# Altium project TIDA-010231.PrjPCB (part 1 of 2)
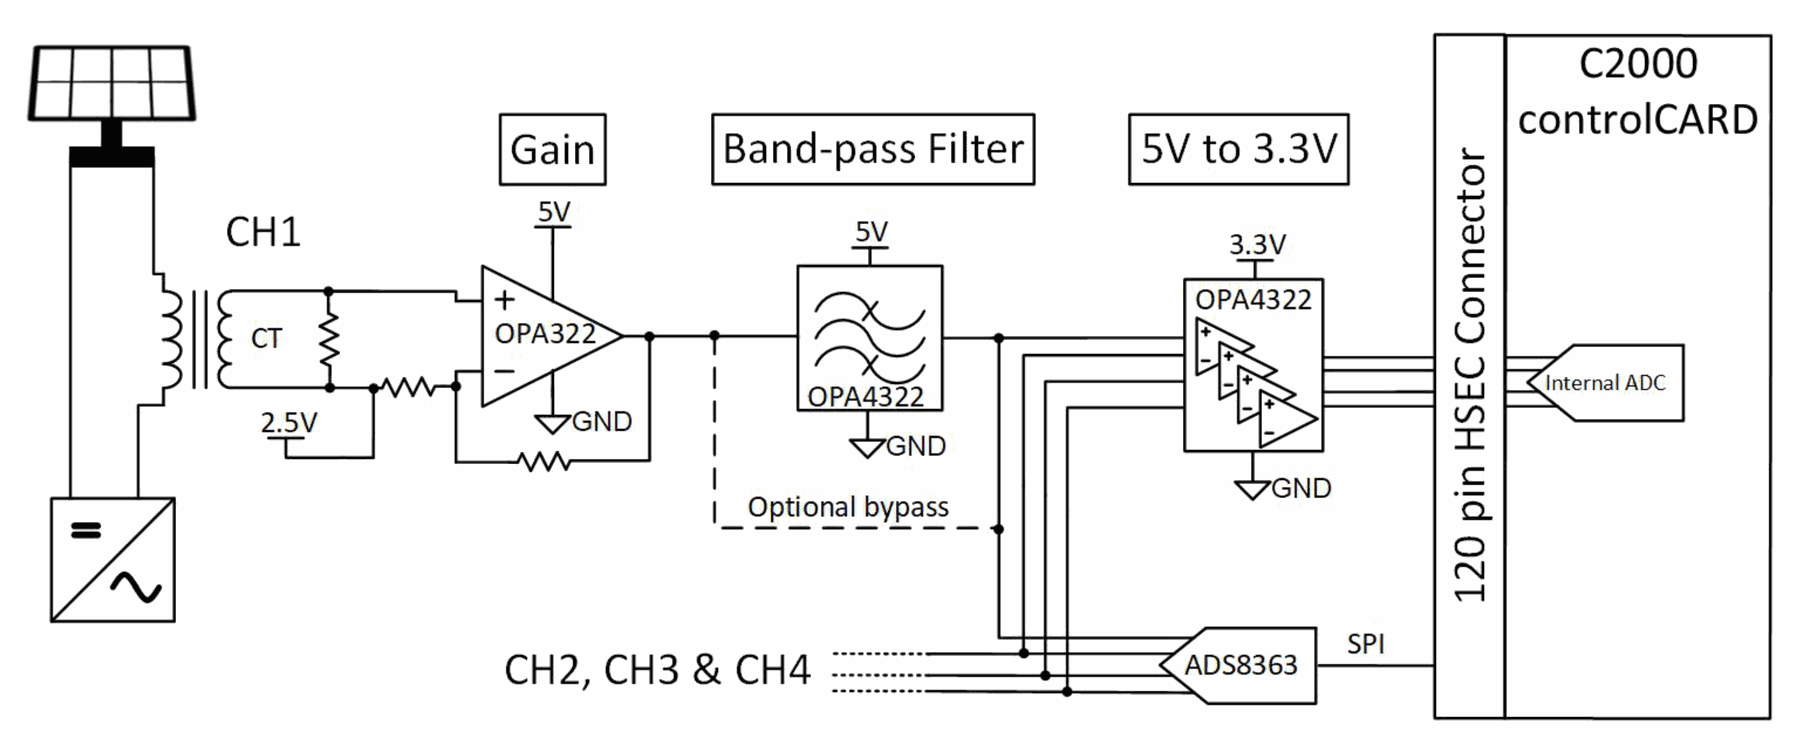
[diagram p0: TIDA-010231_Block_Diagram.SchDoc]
CopyrightYear: 2022; DrawnBy: Andreas Lechner; EVM_orderable: N/A; PCB_Layout: Andreas Lechner; PCB_Rev: E1; PRJ_Customer: Public Release; PRJ_Engineer: Andreas Lechner; PRJ_Number: TIDA-010231; PRJ_Title: TIDA-010231; SCH_Rev: E1; TechSupport: http://www.ti.com/support; TID: TIDA-010231
6 sheets, 296 parts. Net scope: global (net labels, ports and power ports of the same name join across sheets).
Board file: TIDA-010231_PCB.PcbDoc
Sheets:
  TIDA-010231_Block_Diagram.SchDoc
  TIDA-010231_Power.SchDoc
  TIDA-010231_Filter_and_ADC.SchDoc
  TIDA-010231_Current_Transformer.SchDoc
  TIDA-010231_Interface.SchDoc
  TIDA-010231_Hardware.SchDoc

## Sheet TIDA-010231_Block_Diagram.SchDoc: Block Diagram
size 431 x 279 mm; Date: Not shown in title block; ApprovedBy: Not shown in title block; CheckedBy: Not shown in title block; Author: Not shown in title block; CompanyName: Not shown in title block; Engineer: Not shown in title block; Organization: Not shown in title block; Address1: Not shown in title block; Address2: Not shown in title block; Address3: Not shown in title block; Address4: Not shown in title block; DocumentNumber: 1; Revision: Use project parameter SCH_Rev; SheetNumber: 1; SheetTotal: 6; PageSetup: Record=PageOptions¦CenterHorizontal=True¦CenterVertical=True¦PrintScale=1.00¦XCorrection=1.00¦YCorrection=1.00¦PrintKind=0¦BorderSize=5000000¦LeftOffset=0¦BottomOffset=0¦Orientation=2¦PaperLength=1000¦PaperWidth=1000¦Scale=100¦PaperSource=15¦PrintQuality=600¦MediaType=1¦DitherType=10¦PaperKind=Letter¦PrintScaleMode=1

## Sheet TIDA-010231_Power.SchDoc: Power
size 431 x 279 mm; Date: Not shown in title block; ApprovedBy: Not shown in title block; CheckedBy: Not shown in title block; Author: Not shown in title block; CompanyName: Not shown in title block; Engineer: Not shown in title block; Organization: Not shown in title block; Address1: Not shown in title block; Address2: Not shown in title block; Address3: Not shown in title block; Address4: Not shown in title block; DocumentNumber: 2; Revision: Use project parameter SCH_Rev; SheetNumber: 2; SheetTotal: 6; PageSetup: Record=PageOptions¦CenterHorizontal=True¦CenterVertical=True¦PrintScale=1.00¦XCorrection=1.00¦YCorrection=1.00¦PrintKind=0¦BorderSize=5000000¦LeftOffset=0¦BottomOffset=0¦Orientation=2¦PaperLength=1000¦PaperWidth=1000¦Scale=100¦PaperSource=15¦PrintQuality=600¦MediaType=1¦DitherType=10¦PaperKind=Letter¦PrintScaleMode=1
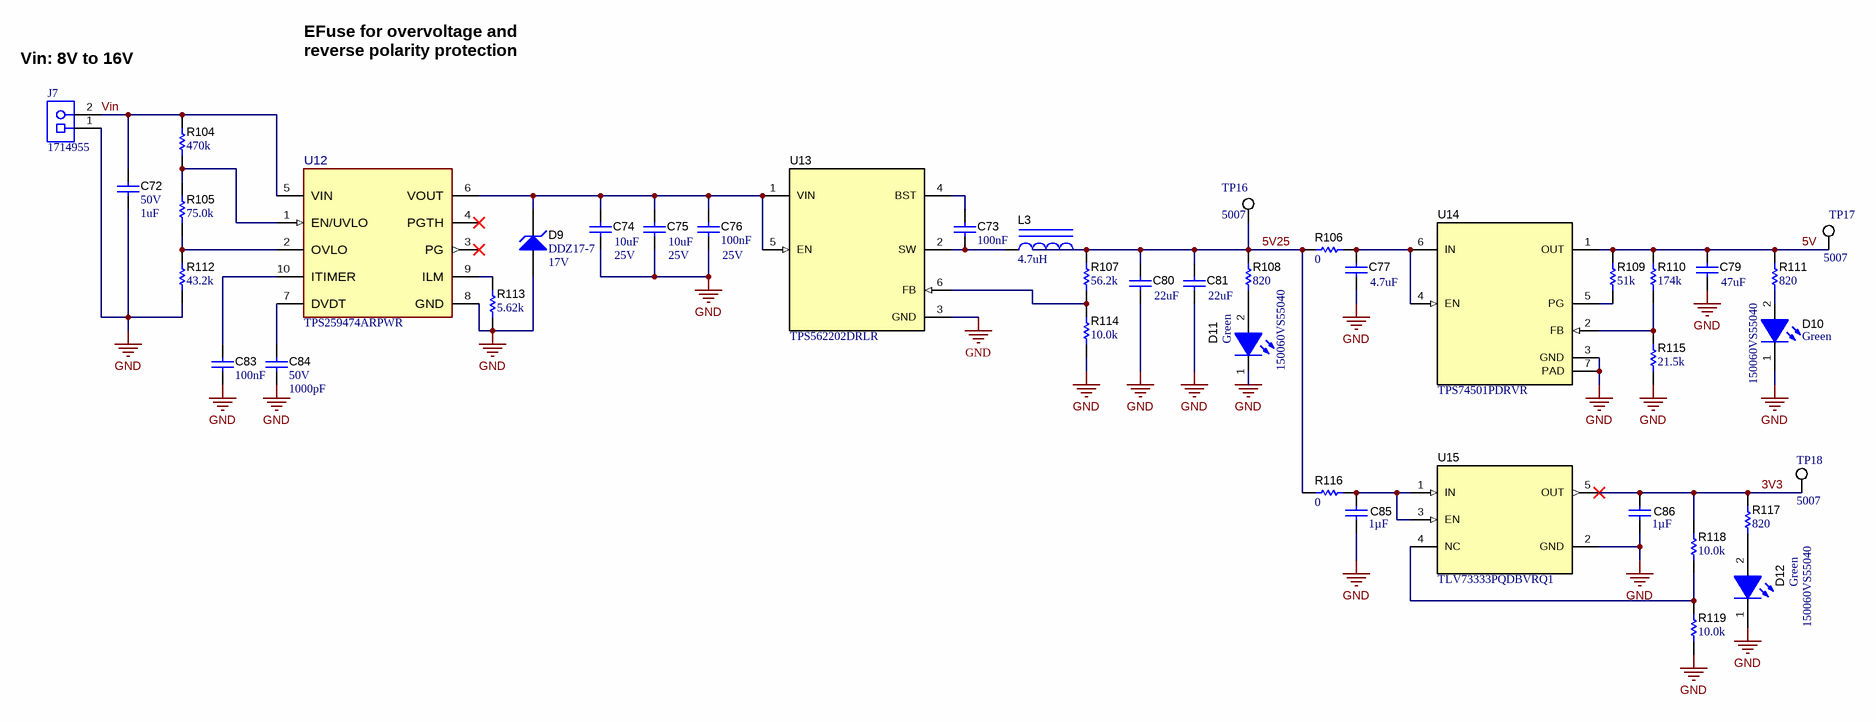
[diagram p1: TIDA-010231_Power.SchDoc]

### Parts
C72  VDC_V: 50V  ValueDisplayed: 1uF  [0603S]  (hidden comment: C1608X5R1H105K080AB)
C73  Cap_F: 100nF  [0603S]  (hidden comment: C0603C104J3RACTU)
C74  Value2: 25V  ValueDisplayed: 10uF  [0805_HV]  (hidden comment: GRM219R61E106MA12)
C75  Value2: 25V  ValueDisplayed: 10uF  [0805_HV]  (hidden comment: GRM219R61E106MA12)
C76  Value2: 25V  Cap_F: 100nF  [0603S]  (hidden comment: C0603C104J3RACTU)
C77  value 4.7uF  [0603S]  (hidden comment: GRM188Z71A475ME15D)
C79  ValueDisplayed: 47uF  [0603S]  (hidden comment: GRM188R60J476ME15D)
C80  ValueDisplayed: 22uF  [0805]  (hidden comment: GRM21BR61A226ME44L)
C81  ValueDisplayed: 22uF  [0805]  (hidden comment: GRM21BR61A226ME44L)
C83  Cap_F: 100nF  [0603S]  (hidden comment: C0603C104J3RACTU)
C84  VDC_V: 50V  ValueDisplayed: 1000pF  [0402S]  (hidden comment: GRM1555C1H102FA01D)
C85  Cap_F: 1µF  [0603S]  (hidden comment: CGA3E1X7R1E105K080AC)
C86  Cap_F: 1µF  [0603S]  (hidden comment: CGA3E1X7R1E105K080AC)
D9  DDZ17-7  value 17V  [SOD-123]
D10  150060VS55040  value Green  [WL-SMCD-0603]
D11  150060VS55040  value Green  [WL-SMCD-0603]
D12  150060VS55040  value Green  [WL-SMCD-0603]
J7  1714955  [Phoenix_1714955]
L3  ValueDisplayed: 4.7uH  [WE-LHMI_7050]  (hidden comment: 74437349047)
R104  ValueDisplayed: 470k  [0603S]  (hidden comment: RC0603FR-07470KL)
R105  ValueDisplayed: 75.0k  [0603S]  (hidden comment: RC0603FR-0775KL)
R106  ValueDisplayed: 0  [0603S]  (hidden comment: RMCF0603ZT0R00)
R107  ValueDisplayed: 56.2k  [0603S]  (hidden comment: CRCW060356K2FKEA)
R108  ValueDisplayed: 820  [0603S]  (hidden comment: CRCW0603820RJNEA)
R109  ValueDisplayed: 51k  [0603S]  (hidden comment: CRCW060351K0JNEA)
R110  ValueDisplayed: 174k  [0603S]  (hidden comment: RT0603BRD07174KL)
R111  ValueDisplayed: 820  [0603S]  (hidden comment: CRCW0603820RJNEA)
R112  ValueDisplayed: 43.2k  [0603S]  (hidden comment: RC0603FR-0743K2L)
R113  ValueDisplayed: 5.62k  [0603S]  (hidden comment: RC0603FR-075K62L)
R114  ValueDisplayed: 10.0k  [0603S]  (hidden comment: CRCW060310K0FKEA)
R115  ValueDisplayed: 21.5k  [0603S]  (hidden comment: RT0603BRD0721K5L)
R116  ValueDisplayed: 0  [0603S]  (hidden comment: RMCF0603ZT0R00)
R117  ValueDisplayed: 820  [0603S]  (hidden comment: CRCW0603820RJNEA)
R118  ValueDisplayed: 10.0k  [0603S]  (hidden comment: CRCW060310K0FKEA)
R119  ValueDisplayed: 10.0k  [0603S]  (hidden comment: CRCW060310K0FKEA)
TP16  5007  [Keystone5007]
TP17  5007  [Keystone5007]
TP18  5007  [Keystone5007]
U12  TPS259474ARPWR  [RPW0010A-MFG]
U13  TPS562202DRLR  [DRL0006A]
U14  TPS74501PDRVR  [DRV0006A]
U15  TLV73333PQDBVRQ1  [DBV0005A_N]

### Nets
GND: C72.2 C74.2 C75.2 C76.2 C77.2 C79.2 C80.1 C81.2 C83.2 C84.2 C85.2 C86.2 D9.2(A) D10.1(K) D11.1(K) D12.1(K) J7.1 R112.1 R113.1 R114.1 R115.1 R119.1 U12.8(GND) U13.3(GND) U14.3(GND) U14.7(PAD) U15.2(GND)
3V3: C86.1 R117.2 R118.2 TP18.1 U15.5(OUT)
5V: C79.1 R109.2 R110.2 R111.2 TP17.1 U14.1(OUT)
5V25: C80.2 C81.1 L3.2 R106.2 R107.2 R108.1 R116.1 TP16.1
Vin: C72.1 J7.2 R104.2 U12.5(VIN)
NetC73_1: C73.1 U13.4(BST)
NetC73_2: C73.2 L3.1 U13.2(SW)
NetC74_1: C74.1 C75.1 C76.1 D9.1(K) U12.6(VOUT) U13.1(VIN) U13.5(EN)
NetC77_1: C77.1 R106.1 U14.4(EN) U14.6(IN)
NetC83_1: C83.1 U12.10(ITIMER)
NetC84_1: C84.1 U12.7(DVDT)
NetC85_1: C85.1 R116.2 U15.1(IN) U15.3(EN)
NetD10_2: D10.2(A) R111.1
NetD11_2: D11.2(A) R108.2
NetD12_2: D12.2(A) R117.1
NetR104_1: R104.1 R105.2 U12.1(EN/UVLO)
NetR105_1: R105.1 R112.2 U12.2(OVLO)
NetR107_1: R107.1 R114.2 U13.6(FB)
NetR109_1: R109.1 U14.5(PG)
NetR110_1: R110.1 R115.2 U14.2(FB)
NetR113_2: R113.2 U12.9(ILM)
NetR118_1: R118.1 R119.2 U15.4(NC)

Not connected (* = marked no-connect by the designer): U12 3(PG)* 4(PGTH)*

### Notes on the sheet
- (near J7) Vin: 8V to 16V
- EFuse for overvoltage and reverse polarity protection

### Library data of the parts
C72 = CMP-0007011-5: CAP, CERM, 1 uF, 50 V, +/- 10%, X5R, 0603; Manufacturer: TDK; TaMin_C: -55°C; ESR_ohm: 5.522m; Polarized: N; SizeAreaWB_mm2: 4.68; Value1: 0.005522 ohm; U/M: EA; Value: 1uF; TaMax_C: 85°C; SizeZ_mm: 1; SizeX_mm: 1.6; SizeY_mm: 0.8; Cap_Case: 0603; SizeArea_mm2: 1.28; Cap_F: 1µF; IRMS_A: 2.2162A; AEC Category: Q200
C73 C83 = CMP-0006856-6: CAP, CERM, 0.1 uF, 25 V, +/- 5%, X7R, 0603; Manufacturer: Kemet; TaMin_C: -55°C; Polarized: N; SizeAreaWB_mm2: 4.68; Value1: Unknown; U/M: EA; Value: 0.1uF; TaMax_C: 125°C; SizeZ_mm: 1; SizeX_mm: 1.6; SizeY_mm: 0.8; Cap_Case: 0603; Value2: 25V; SizeArea_mm2: 1.28; AEC Category: Q200
C74 C75 = CMP-0008207-2: CAP, CERM, 10 uF, 25 V, +/- 20%, X5R, 0805; Manufacturer: MuRata; TaMin_C: -55°C; Polarized: N; SizeAreaWB_mm2: 6.75; Value1: Unknown; U/M: EA; Value: 10uF; TaMax_C: 85°C; SizeZ_mm: 1.45; SizeX_mm: 2; SizeY_mm: 1.25; Cap_Case: 0805; SizeArea_mm2: 2.5; Cap_F: 10µF; AEC Category: Q200
C76 = CMP-0006856-6: CAP, CERM, 0.1 uF, 25 V, +/- 5%, X7R, 0603; Manufacturer: Kemet; TaMin_C: -55°C; Polarized: N; SizeAreaWB_mm2: 4.68; Value1: Unknown; U/M: EA; Value: 0.1uF; TaMax_C: 125°C; SizeZ_mm: 1; SizeX_mm: 1.6; SizeY_mm: 0.8; Cap_Case: 0603; SizeArea_mm2: 1.28; AEC Category: Q200
C77 = CMP-0007498-4: CAP, CERM, 4.7 uF, 10 V, +/- 20%, X7R, 0603; Manufacturer: MuRata; TaMin_C: -55°C; Polarized: N; SizeAreaWB_mm2: 4.68; Value1: Unknown; U/M: EA; TaMax_C: 125°C; SizeZ_mm: 1; SizeX_mm: 1.6; SizeY_mm: 0.8; Cap_Case: 0603; Value2: 10V; SizeArea_mm2: 1.28; AEC Category: Q200
C79 = CMP-0007313-5: CAP, CERM, 47 uF, 6.3 V, +/- 20%, X5R, 0603; Manufacturer: MuRata; TaMin_C: -55°C; Polarized: N; SizeAreaWB_mm2: 4.68; Value1: Unknown; U/M: EA; Value: 47uF; TaMax_C: 85°C; SizeZ_mm: 1; SizeX_mm: 1.6; SizeY_mm: 0.8; Cap_Case: 0603; Value2: 6.3V; SizeArea_mm2: 1.28; Cap_F: 47µF; AEC Category: Q200
C80 C81 = CMP-0008286-2: CAP, CERM, 22 uF, 10 V, +/- 20%, X5R, 0805; Manufacturer: MuRata; TaMin_C: -55°C; Polarized: N; SizeAreaWB_mm2: 6.75; Value1: Unknown; U/M: EA; Value: 22uF; TaMax_C: 85°C; SizeZ_mm: 1.45; SizeX_mm: 2; SizeY_mm: 1.25; Value2: 10V; SizeArea_mm2: 2.5; Cap_F: 22µF; AEC Category: Q200
C84 = CMP-0006411-2: CAP, CERM, 1000 pF, 50 V, +/- 1%, C0G/NP0, 0402; Manufacturer: MuRata; TaMin_C: -55°C; Polarized: N; SizeAreaWB_mm2: 3; Value1: Unknown; U/M: EA; Value: 1000pF; TaMax_C: 125°C; SizeZ_mm: 0.6; SizeX_mm: 1; SizeY_mm: 0.5; Cap_Case: 0402; Cap_F: 1nF; AEC Category: Q200
C85 C86 = CMP-0076705-3: CAP, CERM, 1 µF, 25 V,+/- 10%, X7R, AEC-Q200 Grade 1, 0603; Manufacturer: TDK; SizeAreaWB_mm2: 4.68; SizeArea_mm2: 1.28; AEC Qualified: Y; AEC Category: Q200; Value: 1uF; TaMax_C: 125°C; SizeZ_mm: 1.0; AEC Grade: 1; Polarized: N; TaMin_C: -55°C; SizeY_mm: 0.8; Value2: 25V; U/M: EA; SizeX_mm: 1.6; Cap_Case: 1.6x0.8x0.8mm
D9 = CMP-0085140-1: Diode, Zener, 17 V, 500 mW, SOD-123; Manufacturer: Diodes Inc.; RJA_CperW: 425; Power_W: 500mW; SizeY_mm: 1.7; AEC Category: Q101; SizeAreaWB_mm2: 13.095; SizeX_mm: 3.85; Value1: 0.5W; AEC Qualified: N; SizeZ_mm: 1.35; SizeArea_mm2: 6.545
D10-D12 = CMP-0081648-2: LED, Green, SMD; Manufacturer: Wurth Elektronik; Type: AlInGaP; Vr_V: 5V; SizeZ_mm: 0.5; Tjmax_C: 115°C; Io_A: 20mA; Value1: 0.048W; Vf_V: 2V; SizeArea_mm2: 1.28; Angle: 140; SizeX_mm: 1.6; Ir_A: 10µA; Power_TotalModule: 48mW; SizeAreaWB_mm2: 4.68; SizeY_mm: 0.8
J7 = CMP-0055505-1: Terminal Block, 2x1, 6.35mm, Green, TH; Manufacturer: Phoenix Contact; CNHeader: FALSE; Shrouded: Y; Gender: Female; Row_Count: 1; Pitch_mm: 6.35; CT: TRUE
L3 = CMP-0064108-1: Inductor, Shielded Drum Core, Powdered Iron, 4.7 uH, 5 A, 0.028 ohm, SMD; Manufacturer: Wurth Elektronik; Isat: 11A @ 20% inductance drop; Irms: 5A @ 40C rise; Green_Lifecycle: Active; SizeAreaWB_mm2: 73.96; DCR_ohm: 0.028; Green_REACh: Passed; Value: 4.7uH; Imax_A: 5A; SizeZ_mm: 5; SizeX_mm: 6.6; SizeArea_mm2: 43.56; Ind_H: 4.7µH; AEC Category: Q200
R104 = CMP-0023128-4: RES, 470 k, 1%, 0.1 W, 0603; Manufacturer: Yageo; Power_W: 100mW; TempCo: 100 ppm/C; Value: 470k; SizeX_mm: 1.6; SizeY_mm: 0.8; SizeZ_mm: 1; Value2: 0.1W; SizeArea_mm2: 1.28; AEC Qualified: N; AEC Category: Q200; SizeAreaWB_mm2: 4.68
R105 = CMP-0023267-5: RES, 75.0 k, 1%, 0.1 W, 0603; Manufacturer: Yageo; Power_W: 100mW; TempCo: 100 ppm/C; Value_Code: 75k0; Value: 75.0k; EIA_Code: E96; Res_ohm: 75k; SizeX_mm: 1.6; SizeY_mm: 0.8; SizeZ_mm: 1; Value2: 0.1W; SizeArea_mm2: 1.28; AEC Qualified: N; AEC Category: Q200; SizeAreaWB_mm2: 4.68
R106 R116 = CMP-0023343-3: RES, 0, 1%, 0.1 W, AEC-Q200 Grade 0, 0603; Manufacturer: Stackpole Electronics Inc; Power_W: 100mW; TempCo: ppm/C; U/M: EA; Value: 0; SizeX_mm: 1.6; SizeY_mm: 0.8; SizeZ_mm: 1; Value2: 0.1W; SizeArea_mm2: 1.28; AEC Qualified: Y; AEC Category: Q200
R107 = CMP-0022499-4: RES, 56.2 k, 1%, 0.1 W, AEC-Q200 Grade 0, 0603; Manufacturer: Vishay-Dale; Power_W: 100mW; TempCo: 100 ppm/C; Value_Code: 56k2; Value: 56.2k; EIA_Code: E96; SizeX_mm: 1.6; SizeY_mm: 0.8; SizeZ_mm: 1; Value2: 0.1W; SizeArea_mm2: 1.28; AEC Qualified: Y; AEC Category: Q200; AEC Grade: 0
R108 R111 R117 = CMP-0025859-4: RES, 820, 5%, 0.1 W, AEC-Q200 Grade 0, 0603; Manufacturer: Vishay-Dale; Power_W: 100mW; TempCo: 200 ppm/C; Value_Code: 820R; Value: 820; EIA_Code: E24; SizeX_mm: 1.6; SizeY_mm: 0.8; SizeZ_mm: 1; Value2: 0.1W; SizeArea_mm2: 1.28; AEC Qualified: Y; AEC Category: Q200; AEC Grade: 0
R109 = CMP-0025824-4: RES, 51 k, 5%, 0.1 W, AEC-Q200 Grade 0, 0603; Manufacturer: Vishay-Dale; Power_W: 100mW; TempCo: 200 ppm/C; Value_Code: 51k0; Value: 51k; EIA_Code: E24; SizeX_mm: 1.6; SizeY_mm: 0.8; SizeZ_mm: 1; Value2: 0.1W; SizeArea_mm2: 1.28; AEC Qualified: Y; AEC Category: Q200; AEC Grade: 0
R110 = CMP-0023812-3: RES, 174 k, 0.1%, 0.1 W, 0603; Manufacturer: Yageo America; Power_W: 100mW; TempCo: 25 ppm/C; U/M: EA; Value: 174k; EIA_Code: E192; SizeX_mm: 1.6; SizeY_mm: 0.8; SizeZ_mm: 1; Value2: 0.1W; SizeArea_mm2: 1.28; AEC Category: Q200
R112 = CMP-0023112-5: RES, 43.2 k, 1%, 0.1 W, 0603; Manufacturer: Yageo; Power_W: 100mW; TempCo: 100 ppm/C; Value_Code: 43k2; Value: 43.2k; EIA_Code: E96; SizeX_mm: 1.6; SizeY_mm: 0.8; SizeZ_mm: 1; Value2: 0.1W; SizeArea_mm2: 1.28; AEC Qualified: N; AEC Category: Q200; SizeAreaWB_mm2: 4.68
R113 = CMP-0023202-5: RES, 5.62 k, 1%, 0.1 W, 0603; Manufacturer: Yageo; Power_W: 100mW; TempCo: 100 ppm/C; Value_Code: 5k62; Value: 5.62k; EIA_Code: E96; SizeX_mm: 1.6; SizeY_mm: 0.8; SizeZ_mm: 1; Value2: 0.1W; SizeArea_mm2: 1.28; AEC Qualified: N; AEC Category: Q200; SizeAreaWB_mm2: 4.68
R114 R118 R119 = CMP-0021998-4: RES, 10.0 k, 1%, 0.1 W, AEC-Q200 Grade 0, 0603; Manufacturer: Vishay-Dale; Power_W: 100mW; TempCo: 100 ppm/C; Value_Code: 10k0; Value: 10.0k; EIA_Code: E96; Res_ohm: 10k; SizeX_mm: 1.6; SizeY_mm: 0.8; SizeZ_mm: 1; Value2: 0.1W; SizeArea_mm2: 1.28; AEC Qualified: Y; AEC Category: Q200; AEC Grade: 0
R115 = CMP-0023945-3: RES, 21.5 k, 0.1%, 0.1 W, 0603; Manufacturer: Yageo America; Power_W: 100mW; TempCo: 25 ppm/C; Value_Code: 21k5; U/M: EA; Value: 21.5k; EIA_Code: E192; SizeX_mm: 1.6; SizeY_mm: 0.8; SizeZ_mm: 1; Value2: 0.1W; SizeArea_mm2: 1.28; AEC Category: Q200
TP16-TP18 = CMP-0055144-2: Test Point, Compact, White, TH; Manufacturer: Keystone Electronics; CNHeader: FALSE; Green_Lifecycle: Active; Green_REACh: Passed; ContactFinish: Silver; CT: TRUE
U12 = CMP-0092031-1: 2.7-V to 23-V, 28-mΩ, 5.5-A eFuse with integrated reverse polarity protection 10-VQFN-HR -40 to 125; Manufacturer: Texas Instruments; AEC Qualified: No; SizeZ_mm: 1mm; Reset Type: Active Low; Threshold Voltage: 1.2/1.1V; Standoff Height: 0mm; Output Voltage: 23-43V; Min Supply Voltage: 2.7V; Number Of Outputs: 1; Nominal Supply Current: 74-429uA; TJmax_C: +125°C; Max Supply Voltage: 23V
U13 = CMP-0860978-1: TPS562202DRLR, DRL0006A (SOT-5X3-6); Alternate Manufacturer: Texas Instruments; AEC Category: Q200; AEC Qualified: N; SizeX_mm: 1.6; SizeAreaWB_mm2: 6.76; SizeZ_mm: 0.6; CompType: IC; SizeArea_mm2: 2.56
U14 = CMP-0082614-1: 500-mA LDO With Power-Good, DRV0006A (WSON-6); Alternate PartNumber: TPS74501PDRVT; Alternate Manufacturer: Texas Instruments; SizeAreaWB_mm2: 9; SizeZ_mm: 0.8; SizeX_mm: 2; SizeArea_mm2: 4; CompType: IC; AEC Qualified: N; AEC Category: Q200
U15 = CMP-0860155-1: Automotive capacitor-free 300-mA LDO regulator with foldback current limit for portable devices, DBV0005A (SOT-23-5); Manufacturer: Texas Instruments; SizeAreaWB_mm2: 14.82; SizeArea_mm2: 8.12; SizeY_mm: 2.9; CompType: IC; SizeZ_mm: 1.45; SizeX_mm: 2.8; AEC Category: Q200; AEC Qualified: Y

## Sheet TIDA-010231_Filter_and_ADC.SchDoc: Filter Stage and ADC
size 431 x 279 mm; Date: Not shown in title block; ApprovedBy: Not shown in title block; CheckedBy: Not shown in title block; Author: Not shown in title block; CompanyName: Not shown in title block; Engineer: Not shown in title block; Organization: Not shown in title block; Address1: Not shown in title block; Address2: Not shown in title block; Address3: Not shown in title block; Address4: Not shown in title block; DocumentNumber: 4; Revision: Use project parameter SCH_Rev; SheetNumber: 4; SheetTotal: 6; PageSetup: Record=PageOptions¦CenterHorizontal=True¦CenterVertical=True¦PrintScale=1.00¦XCorrection=1.00¦YCorrection=1.00¦PrintKind=0¦BorderSize=5000000¦LeftOffset=0¦BottomOffset=0¦Orientation=2¦PaperLength=1000¦PaperWidth=1000¦Scale=100¦PaperSource=15¦PrintQuality=600¦MediaType=1¦DitherType=10¦PaperKind=Letter¦PrintScaleMode=1
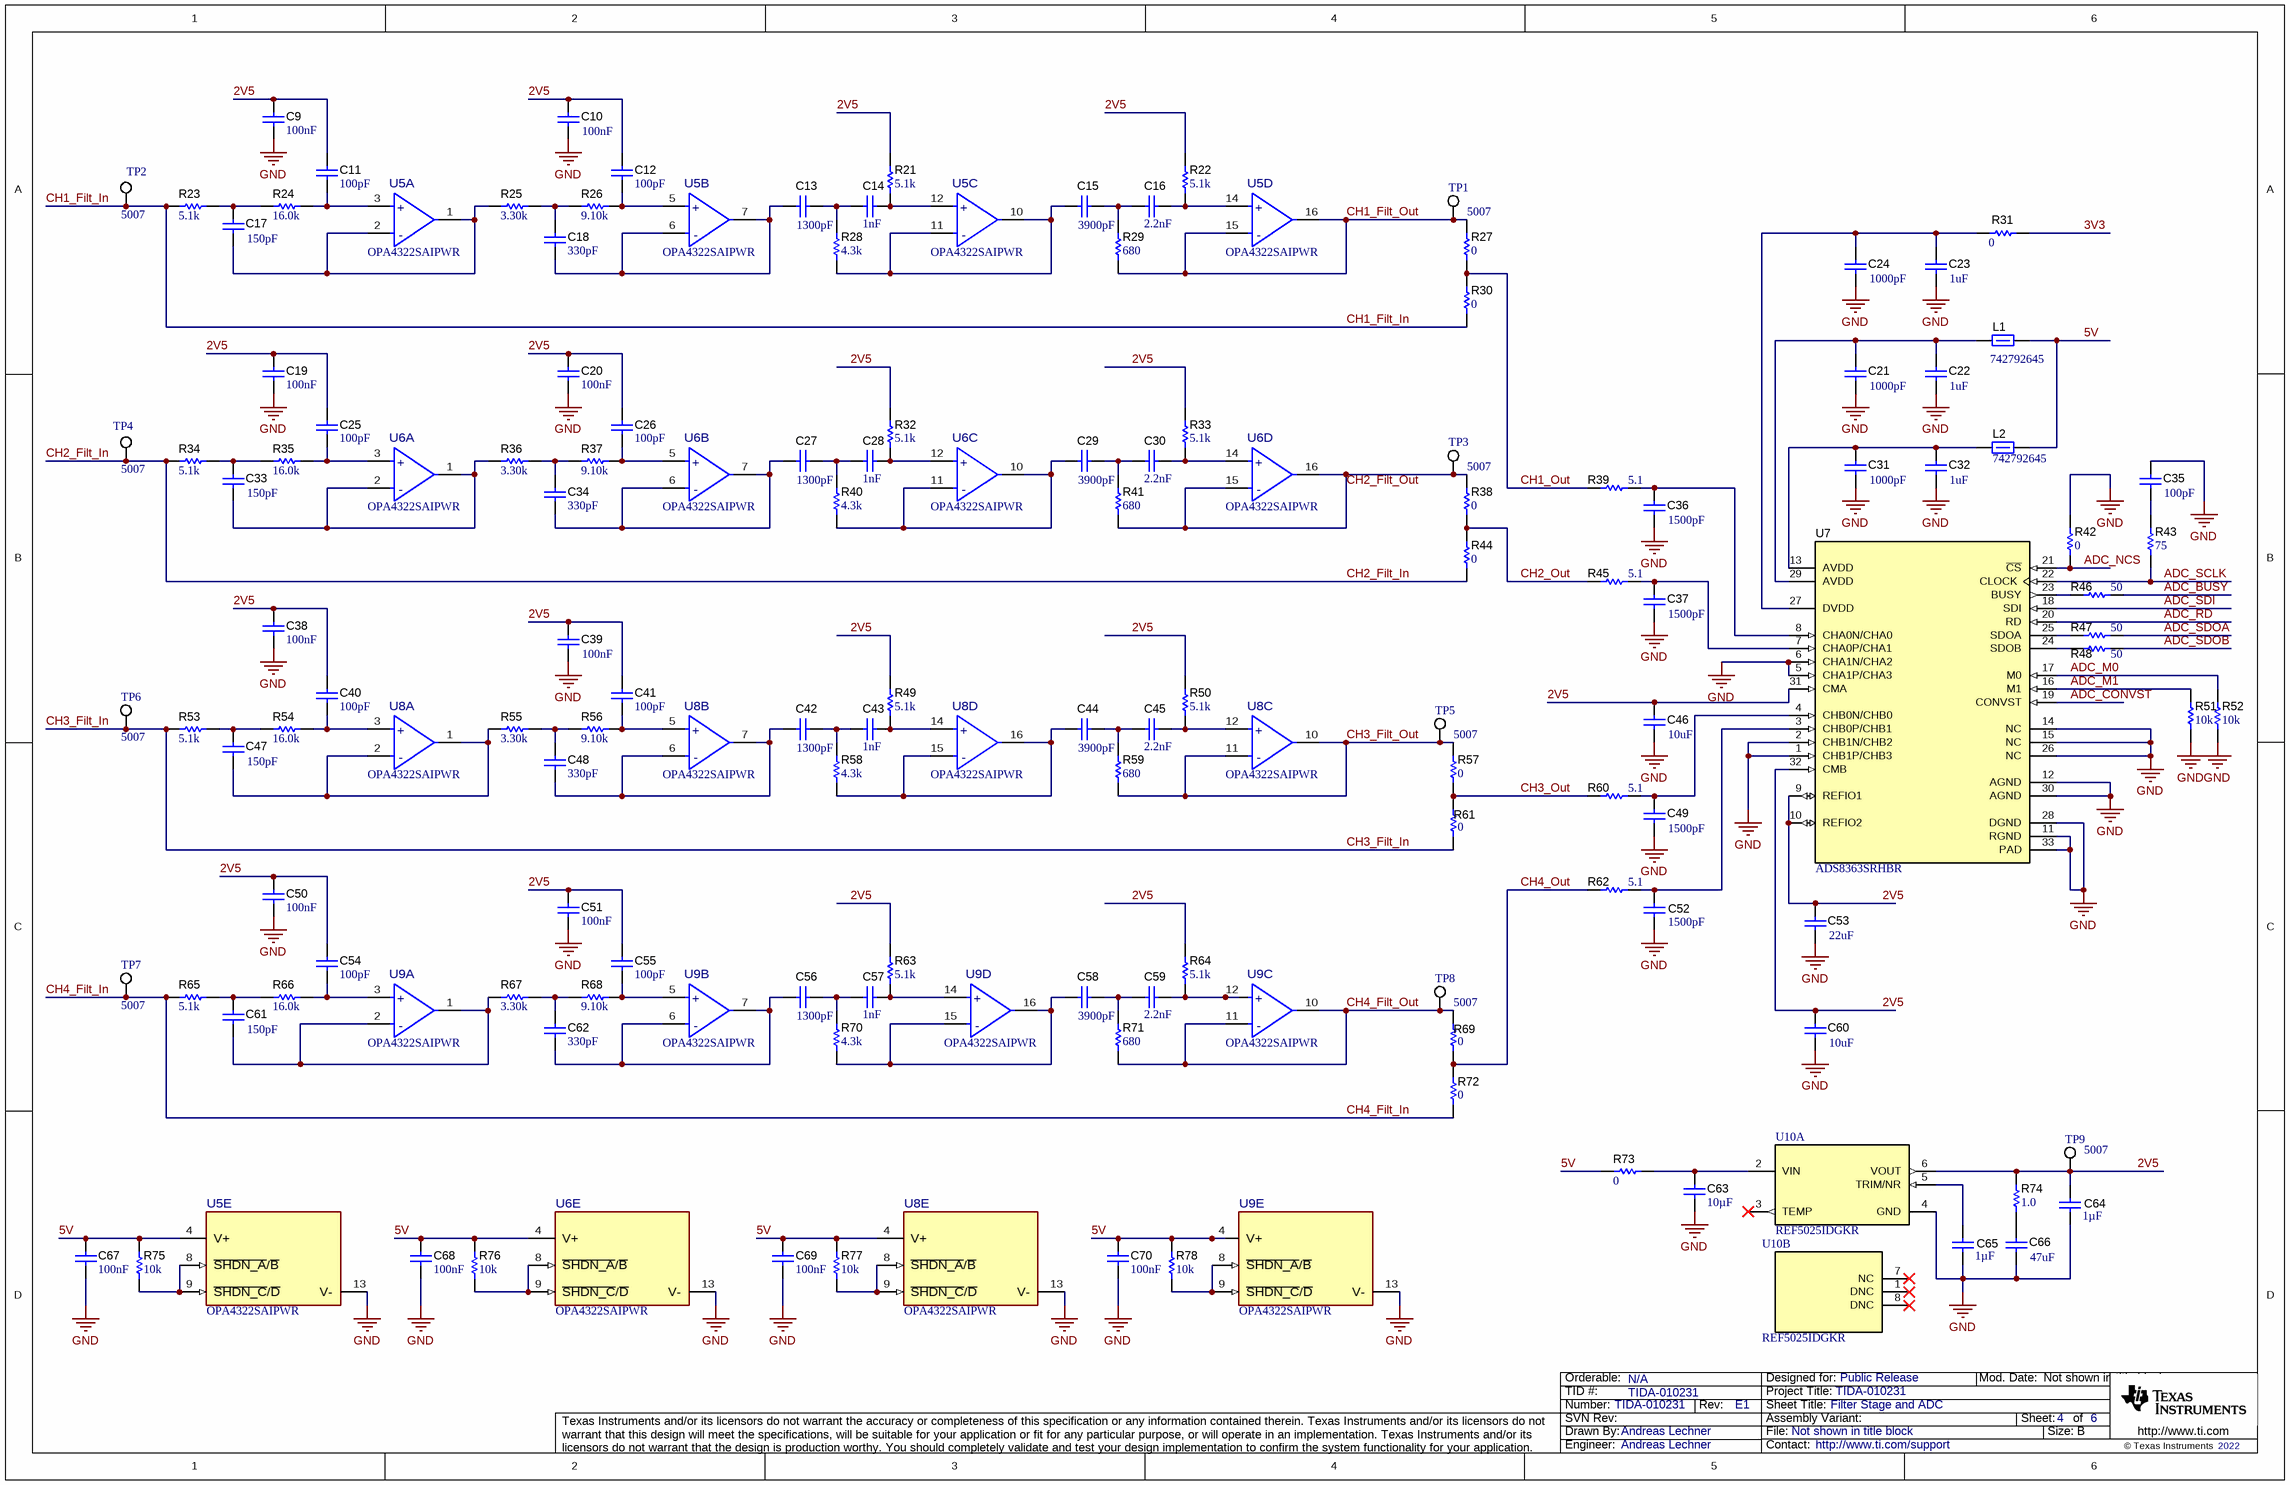
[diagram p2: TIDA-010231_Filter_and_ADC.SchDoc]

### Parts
C9  Cap_F: 100nF  [0603S]  (hidden comment: C0603C104K5RACAUTO)
C10  Cap_F: 100nF  [0603S]  (hidden comment: C0603C104K5RACAUTO)
C11  Cap_F: 100pF  [0603S]  (hidden comment: 06033C101KAT2A)
C12  Cap_F: 100pF  [0603S]  (hidden comment: 06033C101KAT2A)
C13  ValueDisplayed: 1300pF  [0603S]  (hidden comment: GRM1885C1E132JA01D)
C14  Cap_F: 1nF  [0603S]  (hidden comment: GRM188R71H102KA01D)
C15  ValueDisplayed: 3900pF  [0603S]  (hidden comment: GRM1885C1H392JA01D)
C16  Cap_F: 2.2nF  [0603S]  (hidden comment: C0603X222K5RACTU)
C17  ValueDisplayed: 150pF  [0603S]  (hidden comment: GRM1885C1H151JA01D)
C18  ValueDisplayed: 330pF  [0603S]  (hidden comment: 06035A331JAT2A)
C19  Cap_F: 100nF  [0603S]  (hidden comment: C0603C104K5RACAUTO)
C20  Cap_F: 100nF  [0603S]  (hidden comment: C0603C104K5RACAUTO)
C21  ValueDisplayed: 1000pF  [0402S]  (hidden comment: GRM155R71C102KA01D)
C22  ValueDisplayed: 1uF  [0402S]  (hidden comment: GRM155R70J105MA12D)
C23  ValueDisplayed: 1uF  [0402S]  (hidden comment: GRM155R70J105MA12D)
C24  ValueDisplayed: 1000pF  [0402S]  (hidden comment: GRM155R71C102KA01D)
C25  Cap_F: 100pF  [0603S]  (hidden comment: 06033C101KAT2A)
C26  Cap_F: 100pF  [0603S]  (hidden comment: 06033C101KAT2A)
C27  ValueDisplayed: 1300pF  [0603S]  (hidden comment: GRM1885C1E132JA01D)
C28  Cap_F: 1nF  [0603S]  (hidden comment: GRM188R71H102KA01D)
C29  ValueDisplayed: 3900pF  [0603S]  (hidden comment: GRM1885C1H392JA01D)
C30  Cap_F: 2.2nF  [0603S]  (hidden comment: C0603X222K5RACTU)
C31  ValueDisplayed: 1000pF  [0402S]  (hidden comment: GRM155R71C102KA01D)
C32  ValueDisplayed: 1uF  [0402S]  (hidden comment: GRM155R70J105MA12D)
C33  ValueDisplayed: 150pF  [0603S]  (hidden comment: GRM1885C1H151JA01D)
C34  ValueDisplayed: 330pF  [0603S]  (hidden comment: 06035A331JAT2A)
C35  ValueDisplayed: 100pF  [0402S]  (hidden comment: C0402C101J3GACTU)
C36  ValueDisplayed: 1500pF  [0402S]  (hidden comment: GRM155R71H152JA01D)
C37  ValueDisplayed: 1500pF  [0402S]  (hidden comment: GRM155R71H152JA01D)
C38  Cap_F: 100nF  [0603S]  (hidden comment: C0603C104K5RACAUTO)
C39  Cap_F: 100nF  [0603S]  (hidden comment: C0603C104K5RACAUTO)
C40  Cap_F: 100pF  [0603S]  (hidden comment: 06033C101KAT2A)
C41  Cap_F: 100pF  [0603S]  (hidden comment: 06033C101KAT2A)
C42  ValueDisplayed: 1300pF  [0603S]  (hidden comment: GRM1885C1E132JA01D)
C43  Cap_F: 1nF  [0603S]  (hidden comment: GRM188R71H102KA01D)
C44  ValueDisplayed: 3900pF  [0603S]  (hidden comment: GRM1885C1H392JA01D)
C45  Cap_F: 2.2nF  [0603S]  (hidden comment: C0603X222K5RACTU)
C46  ValueDisplayed: 10uF  [0402S]  (hidden comment: GRM155R61A106ME11)
C47  ValueDisplayed: 150pF  [0603S]  (hidden comment: GRM1885C1H151JA01D)
C48  ValueDisplayed: 330pF  [0603S]  (hidden comment: 06035A331JAT2A)
C49  ValueDisplayed: 1500pF  [0402S]  (hidden comment: GRM155R71H152JA01D)
C50  Cap_F: 100nF  [0603S]  (hidden comment: C0603C104K5RACAUTO)
C51  Cap_F: 100nF  [0603S]  (hidden comment: C0603C104K5RACAUTO)
C52  ValueDisplayed: 1500pF  [0402S]  (hidden comment: GRM155R71H152JA01D)
C53  ValueDisplayed: 22uF  [0402S]  (hidden comment: GRM155R60J226ME11D)
C54  Cap_F: 100pF  [0603S]  (hidden comment: 06033C101KAT2A)
C55  Cap_F: 100pF  [0603S]  (hidden comment: 06033C101KAT2A)
C56  ValueDisplayed: 1300pF  [0603S]  (hidden comment: GRM1885C1E132JA01D)
C57  Cap_F: 1nF  [0603S]  (hidden comment: GRM188R71H102KA01D)
C58  ValueDisplayed: 3900pF  [0603S]  (hidden comment: GRM1885C1H392JA01D)
C59  Cap_F: 2.2nF  [0603S]  (hidden comment: C0603X222K5RACTU)
C60  ValueDisplayed: 10uF  [0402S]  (hidden comment: GRM155R61A106ME11)
C61  ValueDisplayed: 150pF  [0603S]  (hidden comment: GRM1885C1H151JA01D)
C62  ValueDisplayed: 330pF  [0603S]  (hidden comment: 06035A331JAT2A)
C63  Cap_F: 10µF  [0603S]  (hidden comment: GRM188Z71A106MA73D)
C64  Cap_F: 1µF  [0603S]  (hidden comment: CGA3E1X7R1E105K080AC)
C65  Cap_F: 1µF  [0603S]  (hidden comment: CGA3E1X7R1E105K080AC)
C66  ValueDisplayed: 47uF  [0603S]  (hidden comment: GRM188R60J476ME15D)
C67  Cap_F: 100nF  [0603S]  (hidden comment: C0603C104K5RACAUTO)
C68  Cap_F: 100nF  [0603S]  (hidden comment: C0603C104K5RACAUTO)
C69  Cap_F: 100nF  [0603S]  (hidden comment: C0603C104K5RACAUTO)
C70  Cap_F: 100nF  [0603S]  (hidden comment: C0603C104K5RACAUTO)
L1  742792645  [0603S]
L2  742792645  [0603S]
R21  ValueDisplayed: 5.1k  [0603S]  (hidden comment: RC0603JR-075K1L)
R22  ValueDisplayed: 5.1k  [0603S]  (hidden comment: RC0603JR-075K1L)
R23  ValueDisplayed: 5.1k  [0603S]  (hidden comment: RC0603JR-075K1L)
R24  ValueDisplayed: 16.0k  [0603S]  (hidden comment: ERJ3EKF1602V)
R25  ValueDisplayed: 3.30k  [0603S]  (hidden comment: CRCW06033K30FKEA)
R26  ValueDisplayed: 9.10k  [0603S]  (hidden comment: RC0603FR-079K1L)
R27  ValueDisplayed: 0  [0603S]  (hidden comment: RMCF0603ZT0R00)
R28  ValueDisplayed: 4.3k  [0603S]  (hidden comment: CRCW06034K30JNEA)
R29  ValueDisplayed: 680  [0603S]  (hidden comment: CRCW0603680RJNEA)
R30  ValueDisplayed: 0  [0603S]  (hidden comment: RMCF0603ZT0R00)
R31  ValueDisplayed: 0  [0402S]  (hidden comment: CRCW04020000Z0ED)
R32  ValueDisplayed: 5.1k  [0603S]  (hidden comment: RC0603JR-075K1L)
R33  ValueDisplayed: 5.1k  [0603S]  (hidden comment: RC0603JR-075K1L)
R34  ValueDisplayed: 5.1k  [0603S]  (hidden comment: RC0603JR-075K1L)
R35  ValueDisplayed: 16.0k  [0603S]  (hidden comment: ERJ3EKF1602V)
R36  ValueDisplayed: 3.30k  [0603S]  (hidden comment: CRCW06033K30FKEA)
R37  ValueDisplayed: 9.10k  [0603S]  (hidden comment: RC0603FR-079K1L)
R38  ValueDisplayed: 0  [0603S]  (hidden comment: RMCF0603ZT0R00)
R39  ValueDisplayed: 5.1  [0402S]  (hidden comment: CRCW04025R10JNED)
R40  ValueDisplayed: 4.3k  [0603S]  (hidden comment: CRCW06034K30JNEA)
R41  ValueDisplayed: 680  [0603S]  (hidden comment: CRCW0603680RJNEA)
R42  ValueDisplayed: 0  [0402S]  (hidden comment: CRCW04020000Z0ED)
R43  ValueDisplayed: 75  [0402S]  (hidden comment: CRCW040275R0JNED)
R44  ValueDisplayed: 0  [0603S]  (hidden comment: RMCF0603ZT0R00)
R45  ValueDisplayed: 5.1  [0402S]  (hidden comment: CRCW04025R10JNED)
R46  ValueDisplayed: 50  [0402S]  (hidden comment: CH0402-50RGFPT)
R47  ValueDisplayed: 50  [0402S]  (hidden comment: CH0402-50RGFPT)
R48  ValueDisplayed: 50  [0402S]  (hidden comment: CH0402-50RGFPT)
R49  ValueDisplayed: 5.1k  [0603S]  (hidden comment: RC0603JR-075K1L)
R50  ValueDisplayed: 5.1k  [0603S]  (hidden comment: RC0603JR-075K1L)
R51  ValueDisplayed: 10k  [0402S]  (hidden comment: CRCW040210K0JNED)
R52  ValueDisplayed: 10k  [0402S]  (hidden comment: CRCW040210K0JNED)
R53  ValueDisplayed: 5.1k  [0603S]  (hidden comment: RC0603JR-075K1L)
R54  ValueDisplayed: 16.0k  [0603S]  (hidden comment: ERJ3EKF1602V)
R55  ValueDisplayed: 3.30k  [0603S]  (hidden comment: CRCW06033K30FKEA)
R56  ValueDisplayed: 9.10k  [0603S]  (hidden comment: RC0603FR-079K1L)
R57  ValueDisplayed: 0  [0603S]  (hidden comment: RMCF0603ZT0R00)
R58  ValueDisplayed: 4.3k  [0603S]  (hidden comment: CRCW06034K30JNEA)
R59  ValueDisplayed: 680  [0603S]  (hidden comment: CRCW0603680RJNEA)
R60  ValueDisplayed: 5.1  [0402S]  (hidden comment: CRCW04025R10JNED)
R61  ValueDisplayed: 0  [0603S]  (hidden comment: RMCF0603ZT0R00)
R62  ValueDisplayed: 5.1  [0402S]  (hidden comment: CRCW04025R10JNED)
R63  ValueDisplayed: 5.1k  [0603S]  (hidden comment: RC0603JR-075K1L)
R64  ValueDisplayed: 5.1k  [0603S]  (hidden comment: RC0603JR-075K1L)
R65  ValueDisplayed: 5.1k  [0603S]  (hidden comment: RC0603JR-075K1L)
R66  ValueDisplayed: 16.0k  [0603S]  (hidden comment: ERJ3EKF1602V)
R67  ValueDisplayed: 3.30k  [0603S]  (hidden comment: CRCW06033K30FKEA)
R68  ValueDisplayed: 9.10k  [0603S]  (hidden comment: RC0603FR-079K1L)
R69  ValueDisplayed: 0  [0603S]  (hidden comment: RMCF0603ZT0R00)
R70  ValueDisplayed: 4.3k  [0603S]  (hidden comment: CRCW06034K30JNEA)
R71  ValueDisplayed: 680  [0603S]  (hidden comment: CRCW0603680RJNEA)
R72  ValueDisplayed: 0  [0603S]  (hidden comment: RMCF0603ZT0R00)
R73  ValueDisplayed: 0  [0603S]  (hidden comment: RMCF0603ZT0R00)
R74  ValueDisplayed: 1.0  [0603S]  (hidden comment: CRCW06031R00JNEA)
R75  ValueDisplayed: 10k  [0402S]  (hidden comment: CRCW040210K0JNED)
R76  ValueDisplayed: 10k  [0402S]  (hidden comment: CRCW040210K0JNED)
R77  ValueDisplayed: 10k  [0402S]  (hidden comment: CRCW040210K0JNED)
R78  ValueDisplayed: 10k  [0402S]  (hidden comment: CRCW040210K0JNED)
TP1  5007  [Keystone5007]
TP2  5007  [Keystone5007]
TP3  5007  [Keystone5007]
TP4  5007  [Keystone5007]
TP5  5007  [Keystone5007]
TP6  5007  [Keystone5007]
TP7  5007  [Keystone5007]
TP8  5007  [Keystone5007]
TP9  5007  [Keystone5007]
U5  OPA4322SAIPWR  [PW0016A-MFG]  (parts A,B,C,D,E of 5)
U6  OPA4322SAIPWR  [PW0016A-MFG]  (parts A,B,C,D,E of 5)
U7  ADS8363SRHBR  [RHB0032E_NV]
U8  OPA4322SAIPWR  [PW0016A-MFG]  (parts A,B,C,D,E of 5)
U9  OPA4322SAIPWR  [PW0016A-MFG]  (parts A,B,C,D,E of 5)
U10  REF5025IDGKR  [DGK0008A_N]  (parts A,B of 2)

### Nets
GND: C9.2 C10.2 C19.2 C20.2 C21.2 C22.2 C23.2 C24.2 C31.2 C32.2 C35.1 C36.2 C37.2 C38.2 C39.2 C46.2 C49.2 C50.2 C51.2 C52.2 C53.1 C60.2 C63.2 C64.2 C65.2 C66.2 C67.2 C68.2 C69.2 C70.2 R42.2 R51.1 R52.1 U5.13(V-) U6.13(V-) U7.1(CHB1P/CHB3) U7.2(CHB1N/CHB2) U7.5(CHA1P/CHA3) U7.6(CHA1N/CHA2) U7.11(RGND) U7.12(AGND) U7.14(NC) U7.15(NC) U7.26(NC) U7.28(DGND) U7.30(AGND) U7.33(PAD) U8.13(V-) U9.13(V-) U10.4(GND)
2V5: C9.1 C10.1 C11.1 C12.1 C19.1 C20.1 C25.1 C26.1 C38.1 C39.1 C40.1 C41.1 C46.1 C50.1 C51.1 C53.2 C54.1 C55.1 C60.1 C64.1 R21.2 R22.2 R32.2 R33.2 R49.2 R50.2 R63.2 R64.2 R74.2 TP9.1 U7.9(REFIO1) U7.10(REFIO2) U7.31(CMA) U7.32(CMB) U10.6(VOUT)
3V3: R31.2
5V: C67.1 C68.1 C69.1 C70.1 L1.2 L2.2 R73.1 R75.2 R76.1 R77.2 R78.2 U5.4(V+) U6.4(V+) U8.4(V+) U9.4(V+)
ADC_BUSY: R46.2
ADC_CONVST: U7.19(CONVST)
ADC_M0: R52.2 U7.17(M0)
ADC_M1: R51.2 U7.16(M1)
ADC_NCS: R42.1 U7.21(~{CS})
ADC_RD: U7.20(RD)
ADC_SCLK: R43.1 U7.22(CLOCK)
ADC_SDI: U7.18(SDI)
ADC_SDOA: R47.2
ADC_SDOB: R48.2
CH1_Filt_In: R23.1 R30.2 TP2.1
CH1_Filt_Out: R27.1 R29.1 TP1.1 U5.15(-IN_D) U5.16(OUT_D)
CH1_Out: R27.2 R30.1 R39.1
CH2_Filt_In: R34.1 R44.2 TP4.1
CH2_Filt_Out: R38.1 R41.1 TP3.1 U6.15(-IN_D) U6.16(OUT_D)
CH2_Out: R38.2 R44.1 R45.1
CH3_Filt_In: R53.1 R61.2 TP6.1
CH3_Filt_Out: R57.1 R59.1 TP5.1 U8.10(OUT_C) U8.11(-IN_C)
CH3_Out: R57.2 R60.1 R61.1
CH4_Filt_In: R65.1 R72.2 TP7.1
CH4_Filt_Out: R69.2 R71.1 TP8.1 U9.10(OUT_C) U9.11(-IN_C)
CH4_Out: R62.1 R69.1 R72.1
NetC11_2: C11.2 R24.2 U5.3(+IN_A)
NetC12_2: C12.2 R26.2 U5.5(+IN_B)
NetC13_1: C13.1 C14.2 R28.2
NetC13_2: C13.2 C18.2 U5.6(-IN_B) U5.7(OUT_B)
NetC14_1: C14.1 R21.1 U5.12(+IN_C)
NetC15_1: C15.1 C16.2 R29.2
NetC15_2: C15.2 R28.1 U5.10(OUT_C) U5.11(-IN_C)
NetC16_1: C16.1 R22.1 U5.14(+IN_D)
NetC17_1: C17.1 R23.2 R24.1
NetC17_2: C17.2 R25.1 U5.1(OUT_A) U5.2(-IN_A)
NetC18_1: C18.1 R25.2 R26.1
NetC21_1: C21.1 C22.1 L1.1 U7.29(AVDD)
NetC23_1: C23.1 C24.1 R31.1 U7.27(DVDD)
NetC25_2: C25.2 R35.2 U6.3(+IN_A)
NetC26_2: C26.2 R37.2 U6.5(+IN_B)
NetC27_1: C27.1 C28.2 R40.2
NetC27_2: C27.2 C34.2 U6.6(-IN_B) U6.7(OUT_B)
NetC28_1: C28.1 R32.1 U6.12(+IN_C)
NetC29_1: C29.1 C30.2 R41.2
NetC29_2: C29.2 R40.1 U6.10(OUT_C) U6.11(-IN_C)
NetC30_1: C30.1 R33.1 U6.14(+IN_D)
NetC31_1: C31.1 C32.1 L2.1 U7.13(AVDD)
NetC33_1: C33.1 R34.2 R35.1
NetC33_2: C33.2 R36.1 U6.1(OUT_A) U6.2(-IN_A)
NetC34_1: C34.1 R36.2 R37.1
NetC35_2: C35.2 R43.2
NetC36_1: C36.1 R39.2 U7.8(CHA0N/CHA0)
NetC37_1: C37.1 R45.2 U7.7(CHA0P/CHA1)
NetC40_2: C40.2 R54.2 U8.3(+IN_A)
NetC41_2: C41.2 R56.2 U8.5(+IN_B)
NetC42_1: C42.1 C43.2 R58.2
NetC42_2: C42.2 C48.2 U8.6(-IN_B) U8.7(OUT_B)
NetC43_1: C43.1 R49.1 U8.14(+IN_D)
NetC44_1: C44.1 C45.2 R59.2
NetC44_2: C44.2 R58.1 U8.15(-IN_D) U8.16(OUT_D)
NetC45_1: C45.1 R50.1 U8.12(+IN_C)
NetC47_1: C47.1 R53.2 R54.1
NetC47_2: C47.2 R55.1 U8.1(OUT_A) U8.2(-IN_A)
NetC48_1: C48.1 R55.2 R56.1
NetC49_1: C49.1 R60.2 U7.4(CHB0N/CHB0)
NetC52_1: C52.1 R62.2 U7.3(CHB0P/CHB1)
NetC54_2: C54.2 R66.2 U9.3(+IN_A)
NetC55_2: C55.2 R68.2 U9.5(+IN_B)
NetC56_1: C56.1 C57.2 R70.2
NetC56_2: C56.2 C62.2 U9.6(-IN_B) U9.7(OUT_B)
NetC57_1: C57.1 R63.1 U9.14(+IN_D)
NetC58_1: C58.1 C59.2 R71.2
NetC58_2: C58.2 R70.1 U9.15(-IN_D) U9.16(OUT_D)
NetC59_1: C59.1 R64.1 U9.12(+IN_C)
NetC61_1: C61.1 R65.2 R66.1
NetC61_2: C61.2 R67.1 U9.1(OUT_A) U9.2(-IN_A)
NetC62_1: C62.1 R67.2 R68.1
NetC63_1: C63.1 R73.2 U10.2(VIN)
NetC65_1: C65.1 U10.5(TRIM/NR)
NetC66_1: C66.1 R74.1
NetR46_1: R46.1 U7.23(BUSY)
NetR47_1: R47.1 U7.25(SDOA)
NetR48_1: R48.1 U7.24(SDOB)
NetR75_1: R75.1 U5.8(~{SHDN_A}/~{B}) U5.9(~{SHDN_C}/~{D})
NetR76_2: R76.2 U6.8(~{SHDN_A}/~{B}) U6.9(~{SHDN_C}/~{D})
NetR77_1: R77.1 U8.8(~{SHDN_A}/~{B}) U8.9(~{SHDN_C}/~{D})
NetR78_1: R78.1 U9.8(~{SHDN_A}/~{B}) U9.9(~{SHDN_C}/~{D})

Not connected (* = marked no-connect by the designer): U10 1(DNC)* 3(TEMP)* 7(NC)* 8(DNC)*

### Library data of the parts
C9 C10 C19 C20 C38 C39 C50 C51 C67-C70 = CMP-0079602-1: CAP, CERM, 0.1 µF, 50 V,+/- 10%, X7R, AEC-Q200 Grade 1, 0603; Manufacturer: Kemet; TaMin_C: -55°C; Polarized: N; SizeAreaWB_mm2: 4.68; U/M: EA; Value: 0.1uF; TaMax_C: 125°C; SizeZ_mm: 1; SizeX_mm: 1.6; SizeY_mm: 0.8; Cap_Case: 0603; Value2: 50V; SizeArea_mm2: 1.28; AEC Qualified: Y; AEC Category: Q200; ValueDisplayed: 0.1µF
C11 C12 C25 C26 C40 C41 C54 C55 = CMP-0006751-4: CAP, CERM, 100 pF, 25 V, +/- 10%, X7R, 0603; Manufacturer: AVX; TaMin_C: -55°C; Polarized: N; SizeAreaWB_mm2: 4.68; Value1: Unknown; U/M: EA; Value: 100pF; TaMax_C: 125°C; SizeZ_mm: 1; SizeX_mm: 1.6; SizeY_mm: 0.8; Cap_Case: 0603; Value2: 25V; SizeArea_mm2: 1.28; AEC Category: Q200
C13 C27 C42 C56 = CMP-0007162-4: CAP, CERM, 1300 pF, 25 V, +/- 5%, C0G/NP0, 0603; Manufacturer: MuRata; TaMin_C: -55°C; Polarized: N; SizeAreaWB_mm2: 4.68; Value1: Unknown; U/M: EA; Value: 1300pF; TaMax_C: 125°C; SizeZ_mm: 1; SizeX_mm: 1.6; SizeY_mm: 0.8; Cap_Case: 0603; Value2: 25V; SizeArea_mm2: 1.28; Cap_F: 1.3nF; AEC Category: Q200
C14 C28 C43 C57 = CMP-0007432-5: CAP, CERM, 1000 pF, 50 V, +/- 10%, X7R, 0603; Manufacturer: MuRata; TaMin_C: -55°C; Polarized: N; SizeAreaWB_mm2: 4.68; Value1: Unknown; U/M: EA; Value: 1000pF; TaMax_C: 125°C; SizeZ_mm: 1; SizeX_mm: 1.6; SizeY_mm: 0.8; Cap_Case: 0603; Value2: 50V; SizeArea_mm2: 1.28; AEC Category: Q200
C15 C29 C44 C58 = CMP-0007216-4: CAP, CERM, 3900 pF, 50 V, +/- 5%, C0G/NP0, 0603; Manufacturer: MuRata; TaMin_C: -55°C; Polarized: N; SizeAreaWB_mm2: 4.68; Value1: Unknown; U/M: EA; Value: 3900pF; TaMax_C: 125°C; SizeZ_mm: 1; SizeX_mm: 1.6; SizeY_mm: 0.8; Cap_Case: 0603; Value2: 50V; SizeArea_mm2: 1.28; Cap_F: 3.9nF; AEC Category: Q200
C16 C30 C45 C59 = CMP-0006983-4: CAP, CERM, 2200 pF, 50 V, +/- 10%, X7R, 0603; Manufacturer: Kemet; TaMin_C: -55°C; Polarized: N; SizeAreaWB_mm2: 4.68; Value1: Unknown; U/M: EA; Value: 2200pF; TaMax_C: 125°C; SizeZ_mm: 1; SizeX_mm: 1.6; SizeY_mm: 0.8; Cap_Case: 0603; Value2: 50V; SizeArea_mm2: 1.28; AEC Category: Q200
C17 C33 C47 C61 = CMP-0007185-4: CAP, CERM, 150 pF, 50 V, +/- 5%, C0G/NP0, 0603; Manufacturer: MuRata; TaMin_C: -55°C; Polarized: N; SizeAreaWB_mm2: 4.68; Value1: Unknown; U/M: EA; Value: 150pF; TaMax_C: 125°C; SizeZ_mm: 1; SizeX_mm: 1.6; SizeY_mm: 0.8; Cap_Case: 0603; Value2: 50V; SizeArea_mm2: 1.28; AEC Category: Q200
C18 C34 C48 C62 = CMP-0006784-4: CAP, CERM, 330 pF, 50 V, +/- 5%, C0G/NP0, 0603; Manufacturer: AVX; TaMin_C: -55°C; ESR_ohm: 71m; Polarized: N; SizeAreaWB_mm2: 4.68; Value1: 0.071 ohm; U/M: EA; Value: 330pF; TaMax_C: 125°C; SizeZ_mm: 1; SizeX_mm: 1.6; SizeY_mm: 0.8; Cap_Case: 0603; Value2: 50V; SizeArea_mm2: 1.28; AEC Category: Q200
C21 C24 C31 = CMP-0006638-2: CAP, CERM, 1000 pF, 16 V, +/- 10%, X7R, 0402; Manufacturer: MuRata; TaMin_C: -55°C; Polarized: N; SizeAreaWB_mm2: 3; Value1: Unknown; U/M: EA; Value: 1000pF; TaMax_C: 125°C; SizeZ_mm: 0.6; SizeX_mm: 1; SizeY_mm: 0.5; Cap_Case: 0402; Value2: 16V; Cap_F: 1nF; AEC Category: Q200
C22 C23 C32 = CMP-0006624-2: CAP, CERM, 1 uF, 6.3 V, +/- 20%, X7R, 0402; Manufacturer: MuRata; TaMin_C: -55°C; Polarized: N; SizeAreaWB_mm2: 3; Value1: Unknown; U/M: EA; Value: 1uF; TaMax_C: 125°C; SizeZ_mm: 0.6; SizeX_mm: 1; SizeY_mm: 0.5; Cap_Case: 0402; Value2: 6.3V; Cap_F: 1µF; AEC Category: Q200
C35 = CMP-0006233-2: CAP, CERM, 100 pF, 25 V, +/- 5%, C0G/NP0, 0402; Manufacturer: Kemet; TaMin_C: -55°C; Polarized: N; SizeAreaWB_mm2: 3; Value1: Unknown; U/M: EA; Value: 100pF; TaMax_C: 125°C; SizeZ_mm: 0.6; SizeX_mm: 1; SizeY_mm: 0.5; Cap_Case: 0402; Value2: 25V; AEC Category: Q200
C36 C37 C49 C52 = CMP-0079620-1: CAP, CERM, 1500 pF, 50 V,+/- 5%, X7R, 0402; Manufacturer: MuRata; TaMin_C: -55°C; Polarized: N; SizeAreaWB_mm2: 3; U/M: EA; Value: 1500pF; TaMax_C: 125°C; SizeZ_mm: 0.6; SizeX_mm: 1; SizeY_mm: 0.5; Cap_Case: 0402; Value2: 50V; Cap_F: 1.5nF; AEC Category: Q200
C46 C60 = CMP-0006564-2: CAP, CERM, 10 uF, 10 V, +/- 20%, X5R, 0402; Manufacturer: MuRata; TaMin_C: -55°C; Polarized: N; SizeAreaWB_mm2: 3; Value1: Unknown; U/M: EA; Value: 10uF; TaMax_C: 85°C; SizeZ_mm: 0.6; SizeX_mm: 1; SizeY_mm: 0.5; Cap_Case: 0402; Value2: 10V; Cap_F: 10µF; AEC Category: Q200
C53 = CMP-0006545-2: CAP, CERM, 22 uF, 6.3 V, +/- 20%, X5R, 0402; Manufacturer: MuRata; TaMin_C: -55°C; Polarized: N; SizeAreaWB_mm2: 3; Value1: Unknown; U/M: EA; Value: 22uF; TaMax_C: 85°C; SizeZ_mm: 0.6; SizeY_mm: 0.5; Cap_Case: 0402; Value2: 6.3V; SizeX_mm: 1; Cap_F: 22µF; AEC Category: Q200
C63 = CMP-0007497-5: CAP, CERM, 10 uF, 10 V, +/- 20%, X7R, 0603; Manufacturer: MuRata; TaMin_C: -55°C; Polarized: N; SizeAreaWB_mm2: 4.68; Value1: Unknown; U/M: EA; Value: 10uF; TaMax_C: 125°C; SizeZ_mm: 1; SizeX_mm: 1.6; SizeY_mm: 0.8; Cap_Case: 0603; Value2: 10V; SizeArea_mm2: 1.28; AEC Category: Q200
C64 C65 = CMP-0076705-3: as C85 on sheet TIDA-010231_Power
C66 = CMP-0007313-5: as C79 on sheet TIDA-010231_Power
L1 L2 = CMP-0003195-2: Ferrite Bead, 470 ohm @ 100 MHz, 1 A, 0603; Manufacturer: Wurth Elektronik; Ztyp@1GHz_Ohm: 211.33; ZTyp@100MHz_Ohm: 470; SizeAreaWB_mm2: 4.68; DCR_ohm: 0.2; Value1: 0.2 ohm; Value: 470 ohm; Imax_A: 1A; SizeZ_mm: 1; SizeX_mm: 1.6; SizeY_mm: 0.8; SizeArea_mm2: 1.28
R21-R23 R32-R34 R49 R50 R53 R63-R65 = CMP-0025932-5: RES, 5.1 k, 5%, 0.1 W, 0603; Manufacturer: Yageo; Power_W: 100mW; TempCo: 100 ppm/C; Value_Code: 5k10; Value: 5.1k; EIA_Code: E24; SizeX_mm: 1.6; SizeY_mm: 0.8; SizeZ_mm: 1; Value2: 0.1W; SizeArea_mm2: 1.28; AEC Qualified: N; AEC Category: Q200; SizeAreaWB_mm2: 4.68
R24 R35 R54 R66 = CMP-0078661-1: RES, 16.0 k, 1%, 0.1 W, AEC-Q200 Grade 0, 0603; Manufacturer: Panasonic; Power_W: 100mW; TempCo: 100 ppm/C; Value_Code: 16k0; Value: 16.0k; Res_ohm: 16k; SizeX_mm: 1.6; SizeY_mm: 0.8; SizeZ_mm: 1; Value2: 0.1W; SizeArea_mm2: 1.28; AEC Qualified: Y; AEC Grade: 0; AEC Category: Q200
R25 R36 R55 R67 = CMP-0082531-1: RES, 3.30 k, 1%, 0.1 W, AEC-Q200 Grade 0, 0603; Manufacturer: Vishay-Dale; Power_W: 100mW; TempCo: 100 ppm/C; SizeAreaWB_mm2: 4.68; Value_Code: 3k30; Value: 3.30k; Res_ohm: 3.3k; SizeX_mm: 1.6; SizeY_mm: 0.8; SizeZ_mm: 1; Value2: 0.1W; SizeArea_mm2: 1.28; AEC Qualified: Y; AEC Grade: 0; AEC Category: Q200
R26 R37 R56 R68 = CMP-0023333-5: RES, 9.10 k, 1%, 0.1 W, 0603; Manufacturer: Yageo; Power_W: 100mW; TempCo: 100 ppm/C; Value_Code: 9k10; Value: 9.10k; Res_ohm: 9.1k; SizeX_mm: 1.6; SizeY_mm: 0.8; SizeZ_mm: 1; Value2: 0.1W; SizeArea_mm2: 1.28; AEC Qualified: N; AEC Category: Q200; SizeAreaWB_mm2: 4.68
R27 R30 R38 R44 R57 R61 R69 R72 R73 = CMP-0023343-3: as R106 on sheet TIDA-010231_Power
R28 R40 R58 R70 = CMP-0025816-4: RES, 4.3 k, 5%, 0.1 W, AEC-Q200 Grade 0, 0603; Manufacturer: Vishay-Dale; Power_W: 100mW; TempCo: 200 ppm/C; Value_Code: 4k30; Value: 4.3k; EIA_Code: E24; SizeX_mm: 1.6; SizeY_mm: 0.8; SizeZ_mm: 1; Value2: 0.1W; SizeArea_mm2: 1.28; AEC Qualified: Y; VDC_V: 75V; AEC Category: Q200; AEC Grade: 0
R29 R41 R59 R71 = CMP-0025841-4: RES, 680, 5%, 0.1 W, AEC-Q200 Grade 0, 0603; Manufacturer: Vishay-Dale; Power_W: 100mW; TempCo: 200 ppm/C; Value_Code: 680R; Value: 680; EIA_Code: E24; SizeX_mm: 1.6; SizeY_mm: 0.8; SizeZ_mm: 1; Value2: 0.1W; SizeArea_mm2: 1.28; AEC Qualified: Y; VDC_V: 75V; AEC Category: Q200; AEC Grade: 0
R31 R42 = CMP-0026822-3: RES, 0, 5%, 0.063 W, AEC-Q200 Grade 0, 0402; Manufacturer: Vishay-Dale; Power_W: 63mW; TempCo: 200 ppm/C; Value_Code: 0000; Value: 0; EIA_Code: E24; SizeX_mm: 1; SizeY_mm: 0.5; SizeZ_mm: 0.6; Value2: 0.063W; AEC Qualified: Y; AEC Category: Q200
R39 R45 R60 R62 = CMP-0026955-3: RES, 5.1, 5%, 0.063 W, AEC-Q200 Grade 0, 0402; Manufacturer: Vishay-Dale; Power_W: 63mW; TempCo: 200 ppm/C; Value_Code: 5R10; Value: 5.1; EIA_Code: E24; SizeX_mm: 1; SizeY_mm: 0.5; SizeZ_mm: 0.6; Value2: 0.063W; AEC Qualified: Y; AEC Category: Q200; AEC Grade: 0
R43 = CMP-0026974-3: RES, 75, 5%, 0.063 W, AEC-Q200 Grade 0, 0402; Manufacturer: Vishay-Dale; Power_W: 63mW; TempCo: 200 ppm/C; Value_Code: 75R0; Value: 75; EIA_Code: E24; SizeX_mm: 1; SizeY_mm: 0.5; SizeZ_mm: 0.6; Value2: 0.063W; AEC Qualified: Y; VDC_V: 50V; AEC Category: Q200; AEC Grade: 0
R46-R48 = CMP-0082623-1: RES, 50, 2%, 0.05 W, 0402; Manufacturer: Vishay Sfernice; Value_Code: 50R0; SizeAreaWB_mm2: 3; SizeArea_mm2: 0.5; AEC Qualified: N; AEC Category: Q200; Value: 50; SizeZ_mm: 0.6; TempCo: 100 ppm/C; Power_W: 50mW; Value2: 0.05W; SizeX_mm: 1
R51 R52 R75-R78 = CMP-0026825-5: RES, 10 k, 5%, 0.063 W, AEC-Q200 Grade 0, 0402; Manufacturer: Vishay-Dale; Power_W: 63mW; TempCo: 200 ppm/C; Value_Code: 10k0; Value: 10k; EIA_Code: E24; SizeX_mm: 1; SizeY_mm: 0.5; SizeZ_mm: 0.6; Value2: 0.063W; AEC Qualified: Y; AEC Category: Q200; AEC Grade: 0
R74 = CMP-0025743-4: RES, 1.0, 5%, 0.1 W, AEC-Q200 Grade 0, 0603; Manufacturer: Vishay-Dale; Power_W: 100mW; TempCo: 200 ppm/C; Value_Code: 1R00; Value: 1.0; EIA_Code: E24; Res_ohm: 1; SizeX_mm: 1.6; SizeY_mm: 0.8; Value2: 0.1W; SizeArea_mm2: 1.28; AEC Qualified: Y; AEC Category: Q200; AEC Grade: 0
TP1-TP9 = CMP-0055144-2: as TP16 on sheet TIDA-010231_Power
U5 U6 U8 U9 = CMP-0093017-1: CMOS Amplifier 4 Circuit Rail-to-Rail 16-TSSOP; Manufacturer: Texas Instruments; TaMin_C: -40°C; Max Dual Supply Voltage: 2.75V; Voltage Gain: 130dB; Min Supply Voltage: 1.8V; TaMax_C: +125°C; Number Of Channels: 4; Input Bias Current: 0.0000002uA; AEC Qualified: No; TJmax_C: +150°C; Standoff Height: 0.05mm; Output Current Per Channel: 65mA; Response Time: 0.32us; Gain Bandwidth: 20MHz; Max Supply Voltage: 5.5V; Min Dual Supply Voltage: 900mV; Nominal Supply Current: 1.4mA; Ciiva Ids: 4369962; Import Ts: 1521861601; Input Offset Voltage: 0.5mV; SizeZ_mm: 1.2mm
U7 = CMP-0075960-1: 16-Bit, 1-MSPS, 4x2/2x2 Simultaneous-Sampling SAR ADC, RHB0032E (VQFN-32); Manufacturer: Texas Instruments; Alternate PartNumber: ADS8363SRHBT; SizeAreaWB_mm2: 49.0; SizeArea_mm2: 25.0; SizeZ_mm: 1.0; SizeY_mm: 5.0; U/M: EA; CompType: IC
U10 = CMP-0032584-2: 3 µVpp/V Noise, 3 ppm/°C Drift Precision Series Voltage Reference, DGK0008A (VSSOP-8); Manufacturer: Texas Instruments; VO(V): 2.5; Initial Accuracy @ 25/deg C(%): 0.05; Eco-Plan: Green (RoHS & no Sb/Br); Iout/Iz(Max)(mA): 10; Iq(Max)(uA): 1000; Temp Coeff(Max)(ppm/ degree C): 3; VI(Max)(V): 18; Rating: Military; VI(Min)(V): 2.7; AEC Category: Q200; AEC Qualified: N; CompType: IC; SizeAreaWB_mm2: 23.6; SizeArea_mm2: 14.7; SizeX_mm: 4.9; SizeZ_mm: 1.1

## Sheet TIDA-010231_Current_Transformer.SchDoc: Current Transformer
size 431 x 279 mm; Date: Not shown in title block; ApprovedBy: Not shown in title block; CheckedBy: Not shown in title block; Author: Not shown in title block; CompanyName: Not shown in title block; Engineer: Not shown in title block; Organization: Not shown in title block; Address1: Not shown in title block; Address2: Not shown in title block; Address3: Not shown in title block; Address4: Not shown in title block; DocumentNumber: 3; Revision: Use project parameter SCH_Rev; SheetNumber: 3; SheetTotal: 6; PageSetup: Record=PageOptions¦CenterHorizontal=True¦CenterVertical=True¦PrintScale=1.00¦XCorrection=1.00¦YCorrection=1.00¦PrintKind=0¦BorderSize=5000000¦LeftOffset=0¦BottomOffset=0¦Orientation=2¦PaperLength=1000¦PaperWidth=1000¦Scale=100¦PaperSource=15¦PrintQuality=600¦MediaType=1¦DitherType=10¦PaperKind=Letter¦PrintScaleMode=1
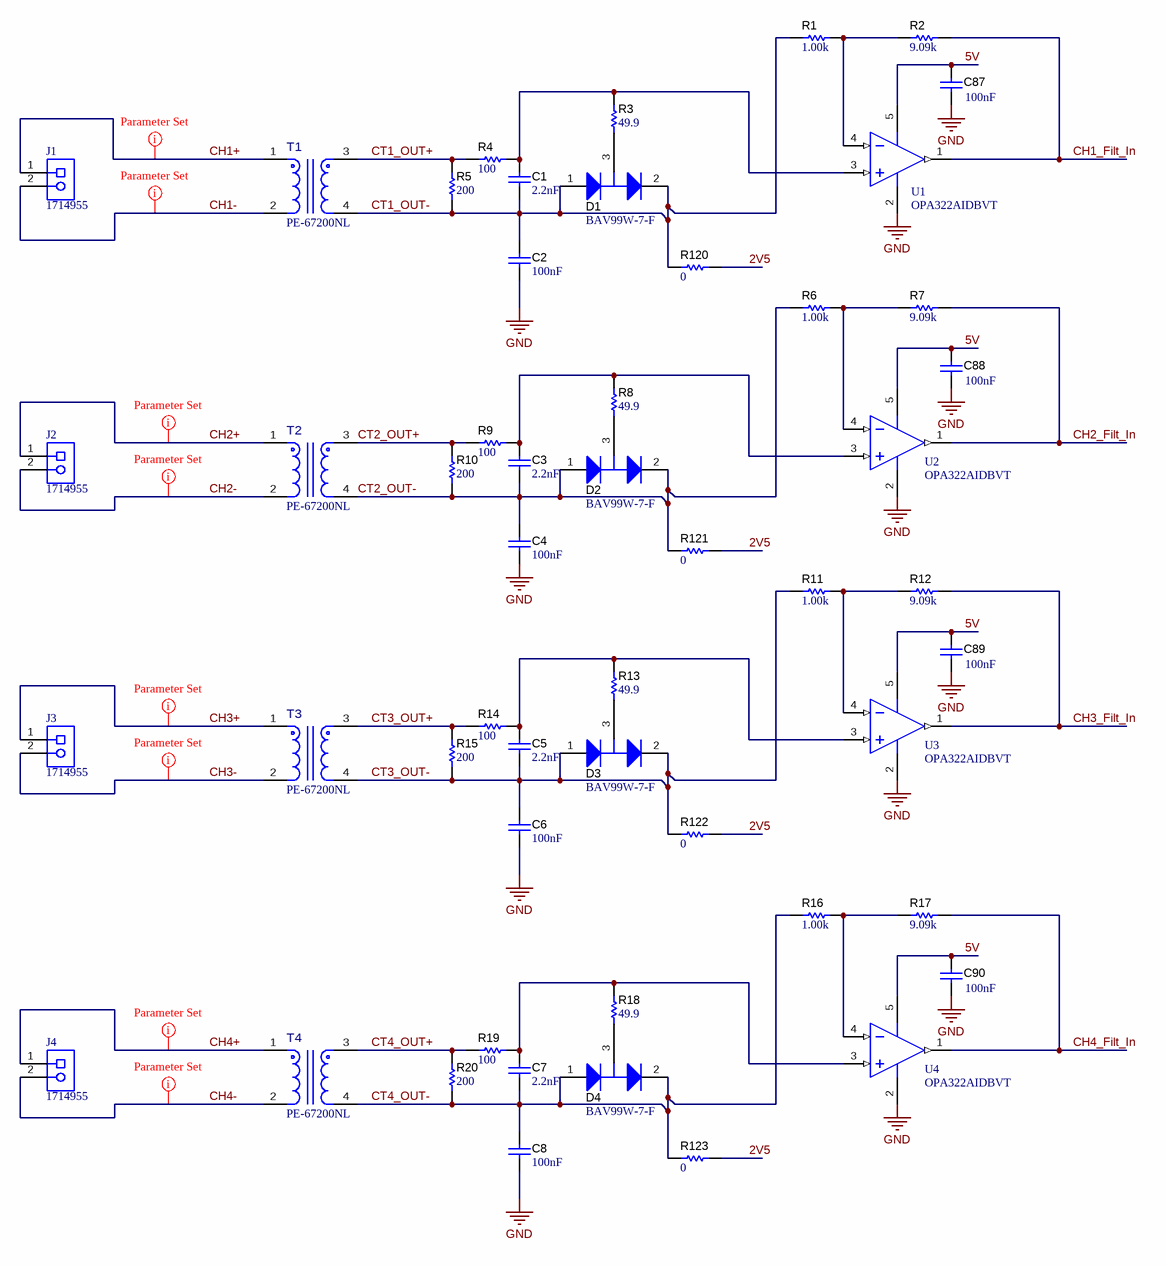
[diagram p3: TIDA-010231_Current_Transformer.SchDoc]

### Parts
C1  Cap_F: 2.2nF  [0603S]  (hidden comment: C0603C222K5RACTU)
C2  Cap_F: 100nF  [0603S]  (hidden comment: C0603C104K5RACAUTO)
C3  Cap_F: 2.2nF  [0603S]  (hidden comment: C0603C222K5RACTU)
C4  Cap_F: 100nF  [0603S]  (hidden comment: C0603C104K5RACAUTO)
C5  Cap_F: 2.2nF  [0603S]  (hidden comment: C0603C222K5RACTU)
C6  Cap_F: 100nF  [0603S]  (hidden comment: C0603C104K5RACAUTO)
C7  Cap_F: 2.2nF  [0603S]  (hidden comment: C0603C222K5RACTU)
C8  Cap_F: 100nF  [0603S]  (hidden comment: C0603C104K5RACAUTO)
C87  Cap_F: 100nF  [0603S]  (hidden comment: C0603C104K5RACAUTO)
C88  Cap_F: 100nF  [0603S]  (hidden comment: C0603C104K5RACAUTO)
C89  Cap_F: 100nF  [0603S]  (hidden comment: C0603C104K5RACAUTO)
C90  Cap_F: 100nF  [0603S]  (hidden comment: C0603C104K5RACAUTO)
D1  BAV99W-7-F  [SOT-323]
D2  BAV99W-7-F  [SOT-323]
D3  BAV99W-7-F  [SOT-323]
D4  BAV99W-7-F  [SOT-323]
J1  1714955  [Phoenix_1714955]
J2  1714955  [Phoenix_1714955]
J3  1714955  [Phoenix_1714955]
J4  1714955  [Phoenix_1714955]
R1  ValueDisplayed: 1.00k  [0603S]  (hidden comment: CRCW06031K00FKEA)
R2  ValueDisplayed: 9.09k  [0603S]  (hidden comment: CRCW06039K09FKEA)
R3  ValueDisplayed: 49.9  [0603S]  (hidden comment: CRCW060349R9FKEA)
R4  ValueDisplayed: 100  [0603S]  (hidden comment: CRCW0603100RFKEA)
R5  ValueDisplayed: 200  [0603S]  (hidden comment: RG1608P-201-B-T5)
R6  ValueDisplayed: 1.00k  [0603S]  (hidden comment: CRCW06031K00FKEA)
R7  ValueDisplayed: 9.09k  [0603S]  (hidden comment: CRCW06039K09FKEA)
R8  ValueDisplayed: 49.9  [0603S]  (hidden comment: CRCW060349R9FKEA)
R9  ValueDisplayed: 100  [0603S]  (hidden comment: CRCW0603100RFKEA)
R10  ValueDisplayed: 200  [0603S]  (hidden comment: RG1608P-201-B-T5)
R11  ValueDisplayed: 1.00k  [0603S]  (hidden comment: CRCW06031K00FKEA)
R12  ValueDisplayed: 9.09k  [0603S]  (hidden comment: CRCW06039K09FKEA)
R13  ValueDisplayed: 49.9  [0603S]  (hidden comment: CRCW060349R9FKEA)
R14  ValueDisplayed: 100  [0603S]  (hidden comment: CRCW0603100RFKEA)
R15  ValueDisplayed: 200  [0603S]  (hidden comment: RG1608P-201-B-T5)
R16  ValueDisplayed: 1.00k  [0603S]  (hidden comment: CRCW06031K00FKEA)
R17  ValueDisplayed: 9.09k  [0603S]  (hidden comment: CRCW06039K09FKEA)
R18  ValueDisplayed: 49.9  [0603S]  (hidden comment: CRCW060349R9FKEA)
R19  ValueDisplayed: 100  [0603S]  (hidden comment: CRCW0603100RFKEA)
R20  ValueDisplayed: 200  [0603S]  (hidden comment: RG1608P-201-B-T5)
R120  ValueDisplayed: 0  [0603S]  (hidden comment: RMCF0603ZT0R00)
R121  ValueDisplayed: 0  [0603S]  (hidden comment: RMCF0603ZT0R00)
R122  ValueDisplayed: 0  [0603S]  (hidden comment: RMCF0603ZT0R00)
R123  ValueDisplayed: 0  [0603S]  (hidden comment: RMCF0603ZT0R00)
T1  PE-67200NL  [FP-PE-67200NL_TRANSFORMER_19MM05_14MM35-MFG]
T2  PE-67200NL  [FP-PE-67200NL_TRANSFORMER_19MM05_14MM35-MFG]
T3  PE-67200NL  [FP-PE-67200NL_TRANSFORMER_19MM05_14MM35-MFG]
T4  PE-67200NL  [FP-PE-67200NL_TRANSFORMER_19MM05_14MM35-MFG]
U1  OPA322AIDBVT  [DBV0005A_N]
U2  OPA322AIDBVT  [DBV0005A_N]
U3  OPA322AIDBVT  [DBV0005A_N]
U4  OPA322AIDBVT  [DBV0005A_N]

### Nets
GND: C2.2 C4.2 C6.2 C8.2 C87.2 C88.2 C89.2 C90.2 U1.2(V-) U2.2(V-) U3.2(V-) U4.2(V-)
2V5: R120.1 R121.1 R122.1 R123.1
5V: C87.1 C88.1 C89.1 C90.1 U1.5(V+) U2.5(V+) U3.5(V+) U4.5(V+)
CH1+: J1.1 T1.1
CH1-: J1.2 T1.2
CH1_Filt_In: R2.2 U1.1(OUT)
CH2+: J2.1 T2.1
CH2-: J2.2 T2.2
CH2_Filt_In: R7.2 U2.1(OUT)
CH3+: J3.1 T3.1
CH3-: J3.2 T3.2
CH3_Filt_In: R12.2 U3.1(OUT)
CH4+: J4.1 T4.1
CH4-: J4.2 T4.2
CH4_Filt_In: R17.2 U4.1(OUT)
CT1_OUT+: R4.1 R5.2 T1.3
CT1_OUT-: C1.2 C2.1 D1.1(A) D1.2(K) R1.1 R5.1 R120.2 T1.4
CT2_OUT+: R9.1 R10.2 T2.3
CT2_OUT-: C3.2 C4.1 D2.1(A) D2.2(K) R6.1 R10.1 R121.2 T2.4
CT3_OUT+: R14.1 R15.2 T3.3
CT3_OUT-: C5.2 C6.1 D3.1(A) D3.2(K) R11.1 R15.1 R122.2 T3.4
CT4_OUT+: R19.1 R20.2 T4.3
CT4_OUT-: C7.2 C8.1 D4.1(A) D4.2(K) R16.1 R20.1 R123.2 T4.4
NetC1_1: C1.1 R3.2 R4.2 U1.3(IN+)
NetC3_1: C3.1 R8.2 R9.2 U2.3(IN+)
NetC5_1: C5.1 R13.2 R14.2 U3.3(IN+)
NetC7_1: C7.1 R18.2 R19.2 U4.3(IN+)
NetD1_3: D1.3(C) R3.1
NetD2_3: D2.3(C) R8.1
NetD3_3: D3.3(C) R13.1
NetD4_3: D4.3(C) R18.1
NetR1_2: R1.2 R2.1 U1.4(IN-)
NetR6_2: R6.2 R7.1 U2.4(IN-)
NetR11_2: R11.2 R12.1 U3.4(IN-)
NetR16_2: R16.2 R17.1 U4.4(IN-)

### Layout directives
net class HighCurrent: CH1+, CH1-, CH2+, CH2-, CH3+, CH3-, CH4+, CH4-

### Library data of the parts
C1 C3 C5 C7 = CMP-0006898-4: CAP, CERM, 2200 pF, 50 V, +/- 10%, X7R, 0603; Manufacturer: Kemet; TaMin_C: -55°C; Polarized: N; SizeAreaWB_mm2: 4.68; Value1: Unknown; U/M: EA; Value: 2200pF; TaMax_C: 125°C; SizeZ_mm: 1; SizeX_mm: 1.6; SizeY_mm: 0.8; Cap_Case: 0603; Value2: 50V; SizeArea_mm2: 1.28; AEC Category: Q200
C2 C4 C6 C8 C87-C90 = CMP-0079602-1: as C9 on sheet TIDA-010231_Filter_and_ADC
D1-D4 = CMP-0077035-2: Diode, Switching, 75 V, 0.15 A, SOT-323; Manufacturer: Diodes Inc.; Vr_V: 75V; SizeX_mm: 2.2; TJmax_C: 150°C; AEC Category: Q101; Vf_V: 1.25V; SizeZ_mm: 1.1; Io_A: 150mA; SizeAreaWB_mm2: 10.24; SizeArea_mm2: 4.84; Green_REACh: Passed; Green_Lifecycle: Active; Value1: 0.15A; Value: 75V
J1-J4 = CMP-0055505-1: as J7 on sheet TIDA-010231_Power
R1 R6 R11 R16 = CMP-0022109-5: RES, 1.00 k, 1%, 0.1 W, AEC-Q200 Grade 0, 0603; Manufacturer: Vishay-Dale; Power_W: 100mW; TempCo: 100 ppm/C; Value_Code: 1k00; Value: 1.00k; EIA_Code: E96; Res_ohm: 1k; SizeX_mm: 1.6; SizeY_mm: 0.8; SizeZ_mm: 1; Value2: 0.1W; SizeArea_mm2: 1.28; AEC Qualified: Y; AEC Category: Q200; AEC Grade: 0
R2 R7 R12 R17 = CMP-0022665-4: RES, 9.09 k, 1%, 0.1 W, AEC-Q200 Grade 0, 0603; Manufacturer: Vishay-Dale; Power_W: 100mW; TempCo: 100 ppm/C; Value_Code: 9k09; Value: 9.09k; EIA_Code: E96; SizeX_mm: 1.6; SizeY_mm: 0.8; SizeZ_mm: 1; Value2: 0.1W; SizeArea_mm2: 1.28; AEC Qualified: Y; AEC Category: Q200; AEC Grade: 0
R3 R8 R13 R18 = CMP-0022448-4: RES, 49.9, 1%, 0.1 W, AEC-Q200 Grade 0, 0603; Manufacturer: Vishay-Dale; Power_W: 100mW; TempCo: 100 ppm/C; Value_Code: 49R9; Value: 49.9; EIA_Code: E96; SizeX_mm: 1.6; SizeY_mm: 0.8; SizeZ_mm: 1; Value2: 0.1W; SizeArea_mm2: 1.28; AEC Qualified: Y; AEC Category: Q200; AEC Grade: 0
R4 R9 R14 R19 = CMP-0021991-4: RES, 100, 1%, 0.1 W, AEC-Q200 Grade 0, 0603; Manufacturer: Vishay-Dale; Power_W: 100mW; TempCo: 100 ppm/C; Value_Code: 100R; Value: 100; EIA_Code: E96; SizeX_mm: 1.6; SizeY_mm: 0.8; SizeZ_mm: 1; Value2: 0.1W; SizeArea_mm2: 1.28; AEC Qualified: Y; AEC Category: Q200; AEC Grade: 0
R5 R10 R15 R20 = CMP-0023462-3: RES, 200, 0.1%, 0.1 W, 0603; Manufacturer: Susumu Co Ltd; Power_W: 100mW; TempCo: 25 ppm/C; Value_Code: 200R; U/M: EA; Value: 200; EIA_Code: E192; SizeX_mm: 1.6; SizeY_mm: 0.8; SizeZ_mm: 1; Value2: 0.1W; SizeArea_mm2: 1.28; AEC Category: Q200
R120-R123 = CMP-0023343-3: as R106 on sheet TIDA-010231_Power
T1-T4 = CMP-0092760-1: 38 A - Current Sense Transformer 10kHz ~ 200kHz 200Ohm Primary, 4.5Ohm Secondary 80 mH Through Hole; Manufacturer: Pulse Electronics Corporation; SizeZ_mm: 19.05mm; Rsec1_ohm: 4.5; Ind_H: 80mH; Ns1toNp: 200:1; DCR_ohm: 200; AEC Qualified: No; Voltage_Isolation_Vrms: 4.25kV; Frequency_Fixed: 10-200kHz
U1-U4 = CMP-0040891-1: 20 MHz, Low Noise, RRIO, CMOS Operational Amplifier with Shutdown, 1.8 to 5.5 V, -40 to 125 degC, 5-pin SOT23 (DBV5), Green (RoHS & no Sb/Br); Manufacturer: Texas Instruments; Rating: Catalog; Iq per channel(Max)(mA): 1.9; Packing: SMALL T&R; Vio (25C)(Max)(mV): 2; IIB(Max)(pA): 10; GBW(Typ)(MHz): 20; Total Supply Voltage(Max)(+5V is 5, +/-5V is 10): 5.5; Sub Family: High Output Current Amplifier (>=50mA), Low Input Bias Current Amp (<=10pA), Low Noise Amp (<=10nV/rtHz), Low Supply Voltage Amplifier (<=2.7V), Precision Amplifier; Offset Drift(Typ)(uV/C): 1.8; Number of Channels: 1; CMRR(Min)(dB): 90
